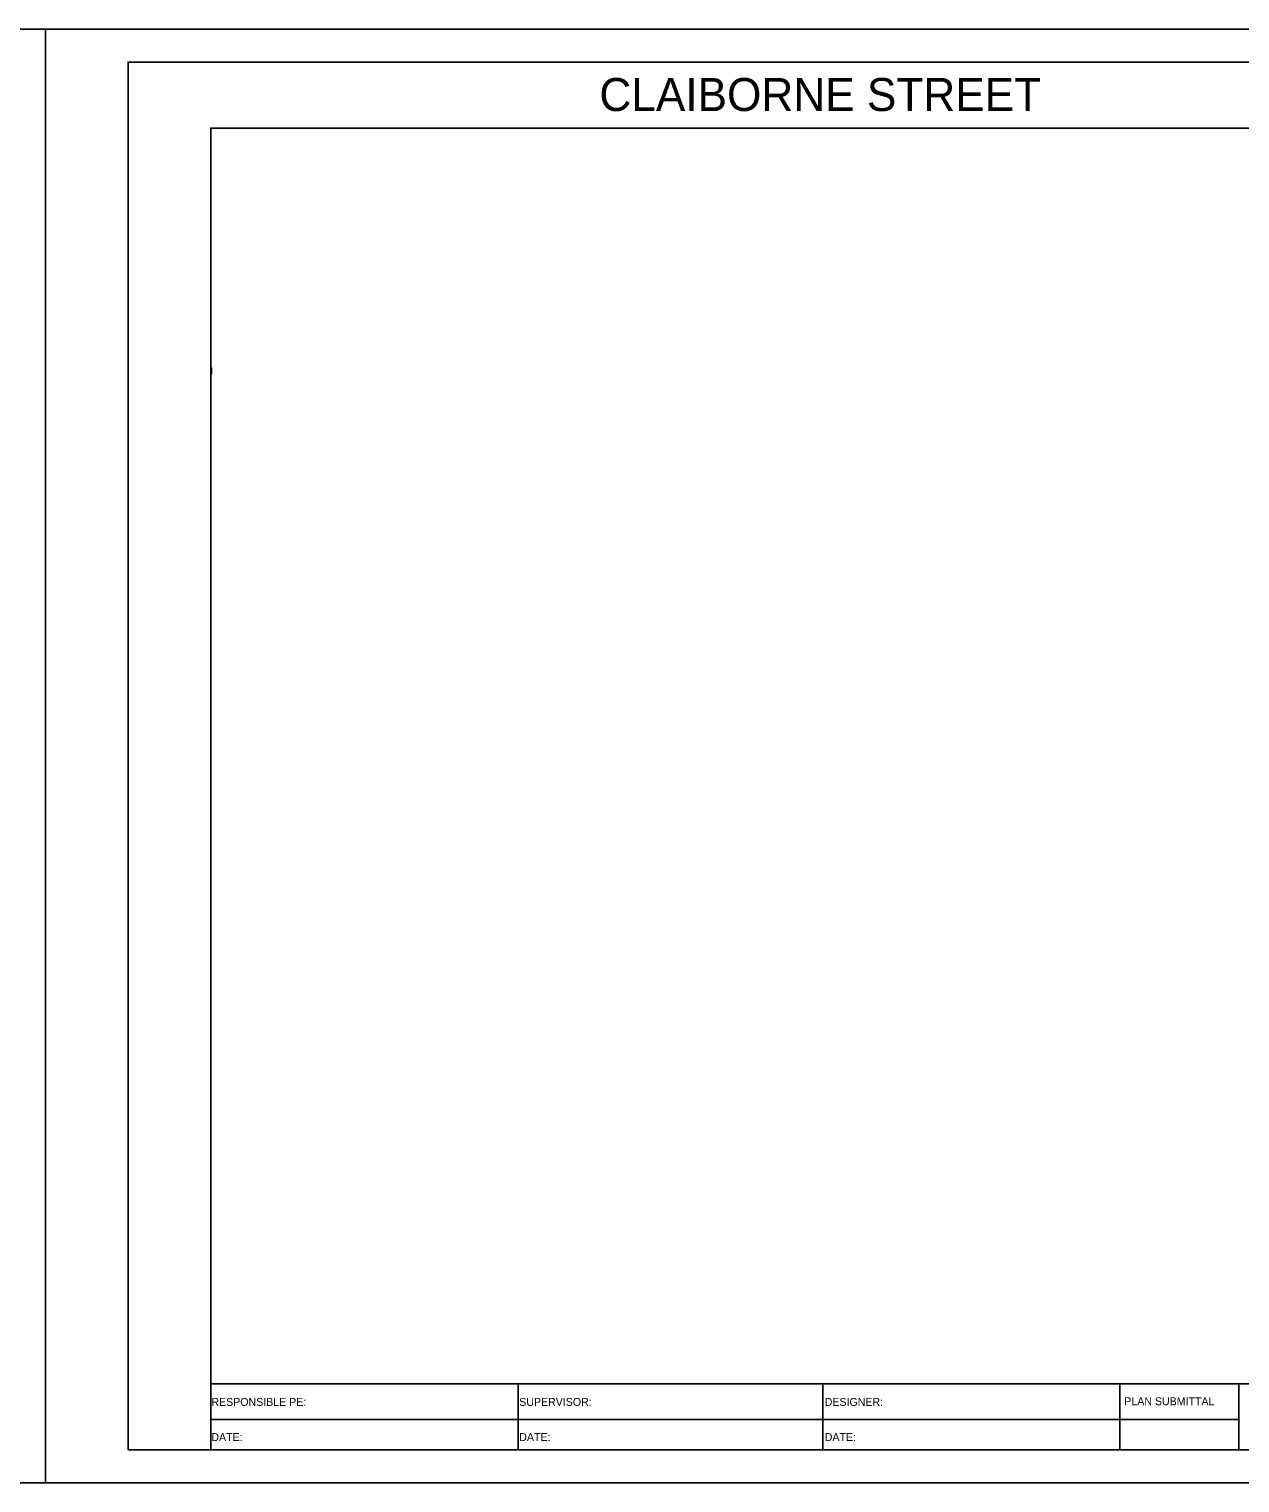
# Model space of a CAD drawing. Extents: x 1797478 to 1802796, y 246529 to 250952.
# Drawn here: x 1802453.5 to 1802636.8, y 250064.4 to 250284.4 of the extents above; entities that cross this region are included whole.
import ezdxf

# ---------------------------------------------------------------- set-up
doc = ezdxf.new("R2010")
doc.units = 0
for name, color, linetype in [('2', 7, 'Continuous'), ('ANNO-SHT', 7, 'Continuous'), ('ANNO-TXT', 7, 'Continuous'), ('AXIS', 7, 'Continuous'), ('DRAINAGE', 7, 'Continuous'), ('Level 1', 7, 'Continuous'), ('Level 62', 7, 'Continuous'), ('SHT-BDR', 7, 'Continuous'), ('SHT-BNDRY', 7, 'Continuous')]:
    doc.layers.add(name, color=color, linetype=linetype)

# ---------------------------------------------------------------- blocks, each defined once
blk = doc.blocks.new('SC47208')
at = {"layer": 'Level 1'}
blk.add_line((0, 0), (0, 0), dxfattribs=at)

msp = doc.modelspace()

# ---------------------------------------------------------------- linework, layer by layer
at = {"layer": '2'}
msp.add_lwpolyline([(1802481.12, 250233.21), (1802481.1, 250232.21)], dxfattribs=at)
msp.add_lwpolyline([(1802481.12, 250233.21), (1802481.1, 250232.21)], dxfattribs=at)
at = {"layer": 'AXIS'}
msp.add_line((1802481, 250189.42), (1802481, 250189.43), dxfattribs=at)
at = {"layer": 'Level 62'}
for points in [[(1802116, 250064.42), (1802456, 250064.42), (1802456, 250284.42), (1802116, 250284.42)], [(1802456, 250064.42), (1802796, 250064.42), (1802796, 250284.42), (1802456, 250284.42)]]:
    msp.add_lwpolyline(points, close=True, dxfattribs=at)
at = {"layer": 'SHT-BDR'}
msp.add_lwpolyline([(1802481, 250079.43), (1802781, 250079.43), (1802781, 250269.43), (1802481, 250269.43)], close=True, dxfattribs=at)
at = {"layer": 'SHT-BNDRY'}
for p, q in [((1802481, 250069.42), (1802481, 250079.43)), ((1802527.52, 250079.43), (1802527.52, 250069.42)), ((1802573.67, 250069.42), (1802573.67, 250079.43)), ((1802618.59, 250069.42), (1802618.59, 250079.43)), ((1802636.63, 250069.42), (1802636.63, 250079.43)), ((1802481, 250074.03), (1802636.63, 250074.03))]:
    msp.add_line(p, q, dxfattribs=at)
msp.add_lwpolyline([(1802468.5, 250069.42), (1802791, 250069.42), (1802791, 250279.42), (1802468.5, 250279.42)], close=True, dxfattribs=at)

# ---------------------------------------------------------------- block references
at = {"layer": 'DRAINAGE', "xscale": 0.2, "yscale": 0.20000000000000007, "rotation": -116.41666666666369}
msp.add_blockref('SC47208', (1802631.32, 250274.62), dxfattribs=at)
msp.add_blockref('SC47208', (1802631.32, 250274.62), dxfattribs=at)

# ---------------------------------------------------------------- texts
at = {"layer": 'ANNO-SHT'}
msp.add_text('            CLAIBORNE STREET            ', height=4.9995, rotation=360, dxfattribs=at).set_placement((1802517.54, 250272.02))
at = {"layer": 'ANNO-TXT'}
for s, p in [('RESPONSIBLE PE:', (1802481.1, 250076.08)), ('SUPERVISOR:', (1802527.7, 250076.08)), ('DESIGNER:', (1802573.94, 250076.08)), ('PLAN SUBMITTAL', (1802619.28, 250076.18)), ('DATE:', (1802481.1, 250070.76)), ('DATE:', (1802527.7, 250070.76)), ('DATE:', (1802573.94, 250070.76))]:
    msp.add_text(s, height=1.2, rotation=360, dxfattribs=at).set_placement(p)

doc.saveas('drawing.dxf')
